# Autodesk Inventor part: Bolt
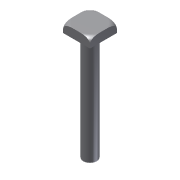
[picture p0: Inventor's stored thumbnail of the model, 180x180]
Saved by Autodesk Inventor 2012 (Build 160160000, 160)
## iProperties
Created: 2009-04
Part Number: Bolt
Document SubType Name: Modeling
Designer: Sham
Density: 1 g/cm^3
Material: Default
Author: Sham
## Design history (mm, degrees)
sketch "Sketch1"
  geometry: L1 (-12, 12)-(12, 12); L2 (12, 12)-(12, -12); L3 (12, -12)-(-12, -12); L4 (-12, -12)-(-12, 12); 1 further point
  constraints: 8 end point, 2 parallel, 2 perpendicular, 1 horizontal, 1 other
  dimensions: "d0" = 24 distance of L1.start L1.end; "d1" = 12 distance from line of L2 point (0, 0); "d2" = 12 distance from line of L1 point (0, 0)
extrude "Extrusion1" new body sketch "Sketch1" distance "d3" = 8; taper "d4" = 0 deg
sketch "Sketch2"
  geometry: C1 r 6 at (0, 0)
  constraints: 1 centre point
  dimensions: "d5" = 12 diameter of C1
extrude "Extrusion2" join sketch "Sketch2" distance "d6" = 96; taper "d7" = 0 deg
workpoint "Work Point1"
workplane "Work Plane1"
sketch "Sketch3"
  geometry: L1 (33.941, 5)-(33.941, 6); L2 (28.941, 0)-(28.405, 0); L3 (16.971, 125.007)-(16.971, -22.043) reference; A1 r 5 centre (28.941, 5) between (28.941, 0) and (33.941, 5); 1 further point
  constraints: 4 end point, 2 point on circle, 2 point on line, 2 tangent, 1 centre point, 1 perpendicular
  dimensions: "d10" = 5 radius of A1
revolve "Revolution1" sketch "Sketch3" stored, may be unused: angle "d12" = 90 deg
body "Solid1"
other parameters: "d11" = 90 deg
